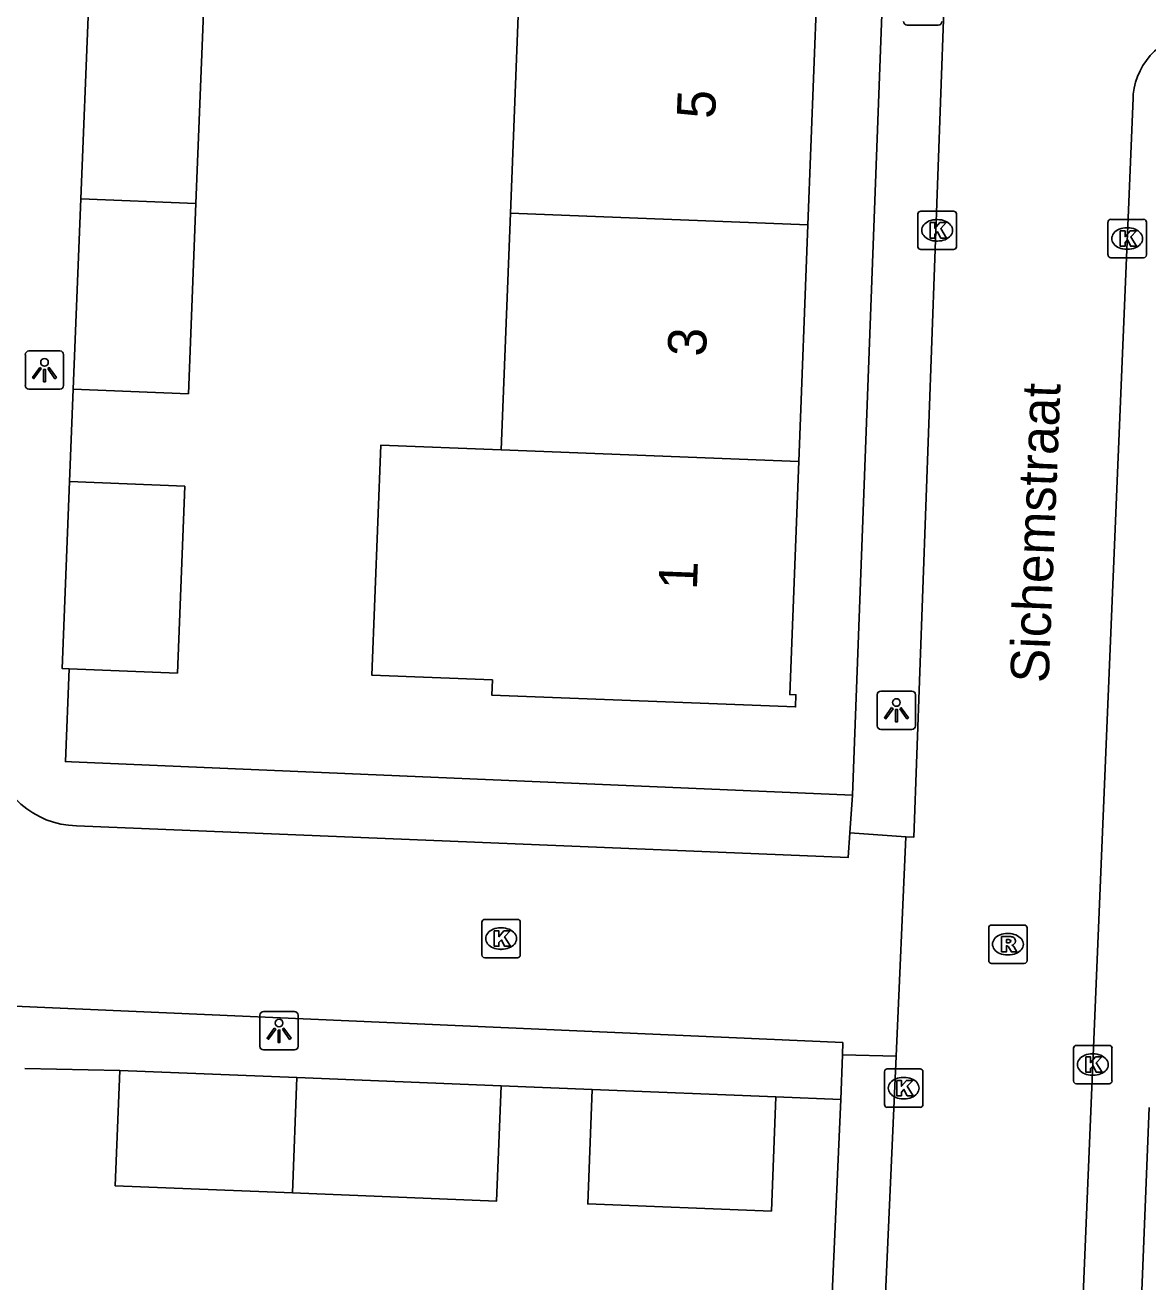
# Model space of a CAD drawing. Extents: x 161355 to 162026, y 386504 to 387459.
# Drawn here: x 161600.69 to 161629.92, y 387313.91 to 387346.64 of the extents above; entities that cross this region are included whole.
import ezdxf

# ---------------------------------------------------------------- set-up
doc = ezdxf.new("R2010")
doc.units = 0
for name, color, linetype in [('IMGEO_Kolk', 7, 'Continuous'), ('IMGEO_Lichtpunt', 7, 'Continuous'), ('IMGEO_Openbare_ruimte_label', 7, 'Continuous'), ('IMGEO_Pand', 7, 'Continuous'), ('IMGEO_Pand_nummerreeks', 7, 'Continuous'), ('IMGEO_Rijbaan_lokaal_open', 7, 'Continuous'), ('IMGEO_Rioolput', 7, 'Continuous'), ('IMGEO_Voetpad_open', 7, 'Continuous')]:
    doc.layers.add(name, color=color, linetype=linetype)

msp = doc.modelspace()

# ---------------------------------------------------------------- linework, layer by layer
at = {"layer": 'IMGEO_Kolk'}
for p, q in [((161623.93, 387340.872), (161623.93, 387341.724)), ((161624.005, 387341.798), (161624.857, 387341.798)), ((161624.418, 387341.578), (161624.443, 387341.578)), ((161624.931, 387341.724), (161624.931, 387340.872)), ((161628.953, 387341.584), (161629.805, 387341.584)), ((161628.878, 387340.658), (161628.878, 387341.51)), ((161629.366, 387341.364), (161629.391, 387341.364)), ((161629.879, 387341.51), (161629.879, 387340.658)), ((161624.441, 387341.018), (161624.416, 387341.018)), ((161624.857, 387340.798), (161624.005, 387340.798)), ((161629.805, 387340.584), (161628.953, 387340.584)), ((161629.389, 387340.804), (161629.364, 387340.804)), ((161612.577, 387322.428), (161612.577, 387323.28)), ((161612.652, 387323.354), (161613.504, 387323.354)), ((161613.578, 387323.28), (161613.578, 387322.428)), ((161613.065, 387323.134), (161613.09, 387323.134)), ((161613.088, 387322.574), (161613.063, 387322.574)), ((161613.504, 387322.354), (161612.652, 387322.354)), ((161627.981, 387319.147), (161627.981, 387319.999)), ((161628.056, 387320.073), (161628.908, 387320.073)), ((161628.982, 387319.999), (161628.982, 387319.147)), ((161628.469, 387319.853), (161628.494, 387319.853)), ((161623.058, 387318.534), (161623.058, 387319.386)), ((161623.133, 387319.46), (161623.985, 387319.46)), ((161624.059, 387319.386), (161624.059, 387318.534)), ((161623.546, 387319.24), (161623.571, 387319.24)), ((161628.908, 387319.073), (161628.056, 387319.073)), ((161628.492, 387319.293), (161628.467, 387319.293)), ((161623.569, 387318.68), (161623.544, 387318.68)), ((161623.985, 387318.46), (161623.133, 387318.46))]:
    msp.add_line(p, q, dxfattribs=at)
for points in [[(161623.93, 387340.872), (161623.93, 387341.724)], [(161624.005, 387341.798), (161624.857, 387341.798)], [(161624.931, 387341.724), (161624.931, 387340.872)], [(161628.953, 387341.584), (161629.805, 387341.584)], [(161624.251, 387341.498), (161624.374, 387341.498), (161624.374, 387341.347), (161624.504, 387341.498), (161624.668, 387341.498), (161624.522, 387341.347), (161624.675, 387341.098), (161624.523, 387341.098), (161624.438, 387341.262), (161624.374, 387341.195), (161624.374, 387341.098), (161624.251, 387341.098), (161624.251, 387341.498)], [(161628.878, 387340.658), (161628.878, 387341.51)], [(161629.199, 387341.284), (161629.322, 387341.284), (161629.322, 387341.133), (161629.452, 387341.284), (161629.616, 387341.284), (161629.47, 387341.133), (161629.623, 387340.884), (161629.471, 387340.884), (161629.386, 387341.048), (161629.322, 387340.981), (161629.322, 387340.884), (161629.199, 387340.884), (161629.199, 387341.284)], [(161629.879, 387341.51), (161629.879, 387340.658)], [(161624.857, 387340.798), (161624.005, 387340.798)], [(161629.805, 387340.584), (161628.953, 387340.584)], [(161612.577, 387322.428), (161612.577, 387323.28)], [(161612.652, 387323.354), (161613.504, 387323.354)], [(161613.578, 387323.28), (161613.578, 387322.428)], [(161612.898, 387323.054), (161613.021, 387323.054), (161613.021, 387322.903), (161613.151, 387323.054), (161613.315, 387323.054), (161613.169, 387322.903), (161613.322, 387322.654), (161613.17, 387322.654), (161613.085, 387322.818), (161613.021, 387322.751), (161613.021, 387322.654), (161612.898, 387322.654), (161612.898, 387323.054)], [(161613.504, 387322.354), (161612.652, 387322.354)], [(161627.981, 387319.147), (161627.981, 387319.999)], [(161628.056, 387320.073), (161628.908, 387320.073)], [(161628.982, 387319.999), (161628.982, 387319.147)], [(161628.302, 387319.773), (161628.425, 387319.773), (161628.425, 387319.622), (161628.555, 387319.773), (161628.719, 387319.773), (161628.573, 387319.622), (161628.726, 387319.373), (161628.574, 387319.373), (161628.489, 387319.537), (161628.425, 387319.47), (161628.425, 387319.373), (161628.302, 387319.373), (161628.302, 387319.773)], [(161623.058, 387318.534), (161623.058, 387319.386)], [(161623.133, 387319.46), (161623.985, 387319.46)], [(161624.059, 387319.386), (161624.059, 387318.534)], [(161623.379, 387319.16), (161623.502, 387319.16), (161623.502, 387319.009), (161623.632, 387319.16), (161623.796, 387319.16), (161623.65, 387319.009), (161623.803, 387318.76), (161623.651, 387318.76), (161623.566, 387318.924), (161623.502, 387318.857), (161623.502, 387318.76), (161623.379, 387318.76), (161623.379, 387319.16)], [(161628.908, 387319.073), (161628.056, 387319.073)], [(161623.985, 387318.46), (161623.133, 387318.46)]]:
    msp.add_lwpolyline(points, dxfattribs=at)
for centre, start, end in [((161624.007, 387341.722), 91.552, 178.448), ((161624.007, 387341.722), 91.552, 178.448), ((161624.855, 387341.722), 1.552, 88.448), ((161624.855, 387341.722), 1.552, 88.448), ((161628.955, 387341.508), 91.552, 178.448), ((161628.955, 387341.508), 91.552, 178.448), ((161629.803, 387341.508), 1.552, 88.448), ((161629.803, 387341.508), 1.552, 88.448), ((161624.007, 387340.874), 181.552, 268.448), ((161624.007, 387340.874), 181.552, 268.448), ((161624.855, 387340.874), 271.552, 358.448), ((161624.855, 387340.874), 271.552, 358.448), ((161628.955, 387340.66), 181.552, 268.448), ((161628.955, 387340.66), 181.552, 268.448), ((161629.803, 387340.66), 271.552, 358.448), ((161629.803, 387340.66), 271.552, 358.448), ((161612.654, 387323.278), 91.552, 178.448), ((161612.654, 387323.278), 91.552, 178.448), ((161613.502, 387323.278), 1.552, 88.448), ((161613.502, 387323.278), 1.552, 88.448), ((161612.654, 387322.43), 181.552, 268.448), ((161612.654, 387322.43), 181.552, 268.448), ((161613.502, 387322.43), 271.552, 358.448), ((161613.502, 387322.43), 271.552, 358.448), ((161628.058, 387319.997), 91.552, 178.448), ((161628.058, 387319.997), 91.552, 178.448), ((161628.906, 387319.997), 1.552, 88.448), ((161628.906, 387319.997), 1.552, 88.448), ((161623.135, 387319.384), 91.552, 178.448), ((161623.135, 387319.384), 91.552, 178.448), ((161623.983, 387319.384), 1.552, 88.448), ((161623.983, 387319.384), 1.552, 88.448), ((161628.058, 387319.149), 181.552, 268.448), ((161628.058, 387319.149), 181.552, 268.448), ((161628.906, 387319.149), 271.552, 358.448), ((161628.906, 387319.149), 271.552, 358.448), ((161623.135, 387318.536), 181.552, 268.448), ((161623.135, 387318.536), 181.552, 268.448), ((161623.983, 387318.536), 271.552, 358.448), ((161623.983, 387318.536), 271.552, 358.448)]:
    msp.add_arc(centre, 0.0765, start, end, dxfattribs=at)
for centre, major_axis, ratio, start_param, end_param in [((161624.417, 387341.298), (-0.387, 0.002), 0.722429, 4.712389, 7.853982), ((161624.442, 387341.298), (-0.39, 0.002), 0.717154, 1.570796, 4.712389), ((161629.365, 387341.084), (-0.387, 0.002), 0.722429, 4.712389, 7.853982), ((161629.39, 387341.084), (-0.39, 0.002), 0.717154, 1.570796, 4.712389), ((161613.064, 387322.854), (-0.387, 0.002), 0.722429, 4.712389, 7.853982), ((161613.089, 387322.854), (-0.39, 0.002), 0.717154, 1.570796, 4.712389), ((161628.468, 387319.573), (-0.387, 0.002), 0.722429, 4.712389, 7.853982), ((161628.493, 387319.573), (-0.39, 0.002), 0.717154, 1.570796, 4.712389), ((161623.545, 387318.96), (-0.387, 0.002), 0.722429, 4.712389, 7.853982), ((161623.57, 387318.96), (-0.39, 0.002), 0.717154, 1.570796, 4.712389)]:
    msp.add_ellipse(centre, major_axis=major_axis, ratio=ratio, start_param=start_param, end_param=end_param, dxfattribs=at)
at = {"layer": 'IMGEO_Lichtpunt'}
for p, q in [((161623.652, 387346.642), (161624.46, 387346.642)), ((161623.652, 387346.642), (161624.46, 387346.642)), ((161600.692, 387338.062), (161600.692, 387337.255)), ((161600.692, 387338.062), (161600.692, 387337.255)), ((161601.594, 387338.157), (161600.786, 387338.157)), ((161601.594, 387338.157), (161600.786, 387338.157)), ((161601.688, 387337.255), (161601.688, 387338.062)), ((161601.688, 387337.255), (161601.688, 387338.062)), ((161600.786, 387337.161), (161601.594, 387337.161)), ((161600.786, 387337.161), (161601.594, 387337.161)), ((161622.871, 387329.204), (161622.871, 387328.397)), ((161622.871, 387329.204), (161622.871, 387328.397)), ((161623.773, 387329.299), (161622.965, 387329.299)), ((161623.773, 387329.299), (161622.965, 387329.299)), ((161623.867, 387328.397), (161623.867, 387329.204)), ((161623.867, 387328.397), (161623.867, 387329.204)), ((161622.965, 387328.303), (161623.773, 387328.303)), ((161622.965, 387328.303), (161623.773, 387328.303)), ((161607.7, 387320.952), (161606.892, 387320.952)), ((161607.7, 387320.952), (161606.892, 387320.952)), ((161606.798, 387320.857), (161606.798, 387320.05)), ((161606.798, 387320.857), (161606.798, 387320.05)), ((161607.794, 387320.05), (161607.794, 387320.857)), ((161607.794, 387320.05), (161607.794, 387320.857)), ((161606.892, 387319.956), (161607.7, 387319.956)), ((161606.892, 387319.956), (161607.7, 387319.956))]:
    msp.add_line(p, q, dxfattribs=at)
for points in [[(161601.066, 387337.726), (161601.105, 387337.698), (161600.917, 387337.436), (161600.879, 387337.463), (161601.066, 387337.726)], [(161601.168, 387337.678), (161601.215, 387337.678), (161601.215, 387337.356), (161601.168, 387337.356), (161601.168, 387337.678)], [(161601.278, 387337.698), (161601.316, 387337.725), (161601.503, 387337.463), (161601.464, 387337.435), (161601.278, 387337.698)], [(161623.245, 387328.868), (161623.284, 387328.84), (161623.096, 387328.578), (161623.058, 387328.605), (161623.245, 387328.868)], [(161623.347, 387328.82), (161623.394, 387328.82), (161623.394, 387328.498), (161623.347, 387328.498), (161623.347, 387328.82)], [(161623.457, 387328.84), (161623.495, 387328.867), (161623.682, 387328.605), (161623.643, 387328.577), (161623.457, 387328.84)], [(161607.172, 387320.521), (161607.211, 387320.493), (161607.023, 387320.231), (161606.985, 387320.258), (161607.172, 387320.521)], [(161607.274, 387320.473), (161607.321, 387320.473), (161607.321, 387320.151), (161607.274, 387320.151), (161607.274, 387320.473)], [(161607.384, 387320.493), (161607.422, 387320.52), (161607.609, 387320.258), (161607.57, 387320.23), (161607.384, 387320.493)]]:
    msp.add_lwpolyline(points, dxfattribs=at)
for centre in [(161601.191, 387337.86), (161623.37, 387329.002), (161607.297, 387320.655)]:
    msp.add_circle(centre, 0.0994, dxfattribs=at)
for centre, start, end in [((161623.652, 387346.736), 180, 270), ((161623.652, 387346.736), 180, 270), ((161624.46, 387346.736), 270, 0), ((161624.46, 387346.736), 270, 360), ((161600.786, 387338.062), 90, 180), ((161600.786, 387338.062), 90, 180), ((161601.594, 387338.062), 0, 90), ((161601.594, 387338.062), 0, 90), ((161600.786, 387337.255), 180, 270), ((161600.786, 387337.255), 180, 270), ((161601.594, 387337.255), 270, 0), ((161601.594, 387337.255), 270, 360), ((161622.965, 387329.204), 90, 180), ((161622.965, 387329.204), 90, 180), ((161623.773, 387329.204), 0, 90), ((161623.773, 387329.204), 0, 90), ((161622.965, 387328.397), 180, 270), ((161622.965, 387328.397), 180, 270), ((161623.773, 387328.397), 270, 0), ((161623.773, 387328.397), 270, 360), ((161606.892, 387320.857), 90, 180), ((161606.892, 387320.857), 90, 180), ((161607.7, 387320.857), 0, 90), ((161607.7, 387320.857), 0, 90), ((161606.892, 387320.05), 180, 270), ((161606.892, 387320.05), 180, 270), ((161607.7, 387320.05), 270, 0), ((161607.7, 387320.05), 270, 360)]:
    msp.add_arc(centre, 0.0946, start, end, dxfattribs=at)
at = {"layer": 'IMGEO_Pand'}
for points in [[(161613.556, 387347.791), (161613.322, 387341.742)], [(161621.065, 387341.443), (161621.299, 387347.492)], [(161602.334, 387347.085), (161602.137, 387342.119)], [(161602.334, 387347.085), (161605.332, 387346.967), (161605.135, 387342)], [(161602.137, 387342.119), (161601.94, 387337.162)], [(161605.135, 387342), (161604.938, 387337.043), (161601.94, 387337.162)], [(161605.135, 387342), (161602.137, 387342.119)], [(161613.322, 387341.742), (161613.084, 387335.58)], [(161613.322, 387341.742), (161621.065, 387341.443)], [(161620.827, 387335.281), (161621.065, 387341.443)], [(161613.084, 387335.58), (161609.945, 387335.701), (161609.713, 387329.71), (161612.852, 387329.589), (161612.837, 387329.193), (161620.743, 387328.887), (161620.755, 387329.203), (161620.592, 387329.209), (161620.827, 387335.281)], [(161613.084, 387335.58), (161620.827, 387335.281)], [(161601.845, 387334.754), (161601.652, 387329.885), (161601.832, 387329.878)], [(161601.845, 387334.754), (161604.843, 387334.635), (161604.65, 387329.767), (161601.832, 387329.878)], [(161607.644, 387316.229), (161603.034, 387316.412), (161603.153, 387319.416)], [(161603.153, 387319.416), (161607.764, 387319.233)], [(161607.644, 387316.229), (161607.764, 387319.233)], [(161613.078, 387319.021), (161612.959, 387316.017), (161607.644, 387316.229)], [(161607.764, 387319.233), (161613.078, 387319.021)], [(161620.233, 387318.735), (161620.116, 387315.756), (161615.334, 387315.944), (161615.451, 387318.923)], [(161615.451, 387318.923), (161620.233, 387318.735)]]:
    msp.add_lwpolyline(points, dxfattribs=at)
at = {"layer": 'IMGEO_Rijbaan_lokaal_open'}
for points in [[(161625.777, 387379.325), (161623.822, 387325.494), (161623.615, 387325.508)], [(161633.556, 387346.338), (161631.402, 387346.446), (161631.242, 387346.447), (161631.083, 387346.433), (161630.926, 387346.406), (161630.772, 387346.364), (161630.623, 387346.309), (161630.478, 387346.241), (161630.341, 387346.16), (161630.211, 387346.067), (161630.09, 387345.963), (161629.979, 387345.849), (161629.878, 387345.725), (161629.789, 387345.593), (161629.712, 387345.453), (161629.648, 387345.307), (161629.598, 387345.156), (161629.561, 387345), (161629.537, 387344.843), (161629.53, 387344.736), (161627.971, 387307.342), (161627.513, 387299.069), (161627.477, 387298.242)], [(161622.159, 387325.608), (161622.111, 387324.962), (161602.02, 387325.792)], [(161622.159, 387325.608), (161623.615, 387325.508)], [(161623.615, 387325.508), (161623.359, 387319.788)], [(161621.97, 387319.829), (161621.972, 387320.147), (161591.499, 387321.489)], [(161623.359, 387319.788), (161621.97, 387319.829)], [(161623.359, 387319.788), (161622.795, 387307.197), (161622.567, 387299.583), (161622.494, 387298.537)]]:
    msp.add_lwpolyline(points, dxfattribs=at)
msp.add_arc((161602.067, 387328.036), 2.244, 188.1195, 268.8001, dxfattribs=at)
at = {"layer": 'IMGEO_Rioolput'}
for p, q in [((161625.772, 387322.281), (161625.772, 387323.133)), ((161625.847, 387323.207), (161626.699, 387323.207)), ((161626.26, 387322.987), (161626.285, 387322.987)), ((161626.773, 387323.133), (161626.773, 387322.281)), ((161626.283, 387322.427), (161626.258, 387322.427)), ((161626.699, 387322.207), (161625.847, 387322.207))]:
    msp.add_line(p, q, dxfattribs=at)
for points in [[(161625.772, 387322.281), (161625.772, 387323.133)], [(161625.847, 387323.207), (161626.699, 387323.207)], [(161626.361, 387322.905), (161626.109, 387322.907), (161626.109, 387322.507)], [(161626.773, 387323.133), (161626.773, 387322.281)], [(161626.109, 387322.507), (161626.233, 387322.507), (161626.233, 387322.669), (161626.244, 387322.669)], [(161626.287, 387322.826), (161626.233, 387322.826), (161626.233, 387322.745)], [(161626.233, 387322.745), (161626.285, 387322.745)], [(161626.291, 387322.64), (161626.362, 387322.507), (161626.502, 387322.507), (161626.437, 387322.633)], [(161626.699, 387322.207), (161625.847, 387322.207)]]:
    msp.add_lwpolyline(points, dxfattribs=at)
for centre, radius, start, end in [((161625.849, 387323.131), 0.0765, 91.552, 178.448), ((161625.849, 387323.131), 0.0765, 91.552, 178.448), ((161626.36, 387322.795), 0.109, 350.3612, 89.416), ((161626.697, 387323.131), 0.0765, 1.552, 88.448), ((161626.697, 387323.131), 0.0765, 1.552, 88.448), ((161626.243, 387322.616), 0.0533, 26.0293, 88.6989), ((161626.269, 387322.934), 0.19, 274.7715, 282.9687), ((161626.293, 387322.73), 0.0964, 77.0061, 93.1865), ((161626.307, 387322.787), 0.0378, 276.6634, 79.6772), ((161626.358, 387322.795), 0.112, 277.5842, 350.9817), ((161626.342, 387322.58), 0.108, 29.5134, 73.7905), ((161625.849, 387322.283), 0.0765, 181.552, 268.448), ((161625.849, 387322.283), 0.0765, 181.552, 268.448), ((161626.697, 387322.283), 0.0765, 271.552, 358.448), ((161626.697, 387322.283), 0.0765, 271.552, 358.448)]:
    msp.add_arc(centre, radius, start, end, dxfattribs=at)
for centre, major_axis, ratio, start_param, end_param in [((161626.259, 387322.707), (-0.387, 0.002), 0.722429, 4.712389, 7.853982), ((161626.284, 387322.707), (-0.39, 0.002), 0.717154, 1.570796, 4.712389)]:
    msp.add_ellipse(centre, major_axis=major_axis, ratio=ratio, start_param=start_param, end_param=end_param, dxfattribs=at)
at = {"layer": 'IMGEO_Voetpad_open'}
for points in [[(161624.213, 387379.383), (161624.174, 387378.353), (161622.224, 387326.585)], [(161601.94, 387337.162), (161601.845, 387334.754)], [(161601.832, 387329.878), (161601.736, 387327.465), (161601.89, 387327.458), (161622.224, 387326.585)], [(161622.224, 387326.585), (161622.159, 387325.608)], [(161621.97, 387319.829), (161621.926, 387318.66)], [(161600.682, 387319.474), (161603.153, 387319.416)], [(161613.078, 387319.021), (161615.451, 387318.923)], [(161621.926, 387318.66), (161620.975, 387297.434), (161620.97, 387297.358), (161620.95, 387297.212), (161620.918, 387297.068), (161620.873, 387296.928), (161620.815, 387296.793), (161620.746, 387296.663), (161620.665, 387296.54), (161620.573, 387296.424), (161620.472, 387296.317), (161620.361, 387296.22), (161620.243, 387296.133), (161620.116, 387296.057), (161619.984, 387295.992), (161619.846, 387295.94), (161619.705, 387295.9), (161619.56, 387295.873), (161619.413, 387295.859), (161619.266, 387295.858)], [(161620.233, 387318.735), (161621.926, 387318.66)], [(161629.952, 387318.458), (161629.122, 387297.833), (161629.123, 387297.592), (161629.146, 387297.352), (161629.19, 387297.114), (161629.255, 387296.882), (161629.341, 387296.657), (161629.446, 387296.44), (161629.57, 387296.233), (161629.713, 387296.038), (161629.872, 387295.857), (161630.047, 387295.691), (161630.235, 387295.54), (161630.437, 387295.408), (161630.649, 387295.294), (161630.871, 387295.199), (161631.101, 387295.125), (161631.336, 387295.071), (161631.575, 387295.039)]]:
    msp.add_lwpolyline(points, dxfattribs=at)

# ---------------------------------------------------------------- texts
at = {"layer": 'IMGEO_Openbare_ruimte_label'}
msp.add_text('Sichemstraat', height=1, rotation=87.7071, dxfattribs=at).set_placement((161627.331, 387329.498))
at = {"layer": 'IMGEO_Pand_nummerreeks'}
for s, rotation, p in [('5', 87.7854, (161618.649, 387344.192)), ('3', 87.7854, (161618.41, 387338.001)), ('1', 87.7829, (161618.175, 387331.926))]:
    msp.add_text(s, height=1, rotation=rotation, dxfattribs=at).set_placement(p)

doc.saveas('drawing.dxf')
